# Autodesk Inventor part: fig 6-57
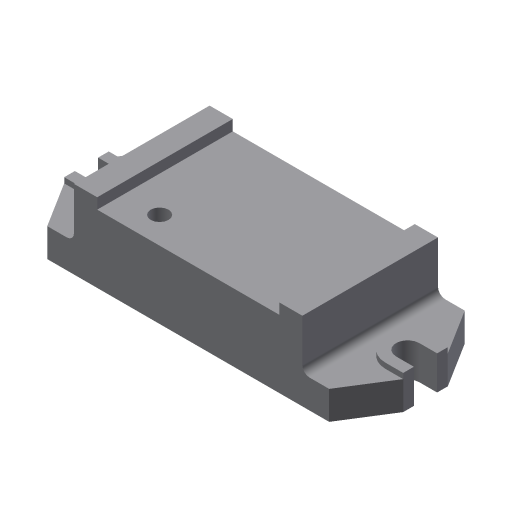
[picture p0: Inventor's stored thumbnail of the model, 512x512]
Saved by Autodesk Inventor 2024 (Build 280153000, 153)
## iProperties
Shininess: 77.0
Angle Display Precision: 2
Document Length Units: 11269
Document Angle Units: 11279
Document Time Units: 11290
Document Mass Units: 11283
Document Length Units Precision: 3
Document Angle Units Precision: 2
Created: 2001-12
Part Number: fig 6-57
Document SubType Name: Modeling
Designer: Renu Muthoo
Density: 1 g/cm^3
Material: Generic
Appearance: Default
Density: 0.0
Volumn: 0.0
Area: 0.0
PropertySet Name: Model Information
Control State: 0
Master: False
Checked Out: False
Author: Renu Muthoo
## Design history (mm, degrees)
sketch "Sketch3"
  geometry: L1 (-59.119, -24.322)-(-59.119, 19.678); L2 (-59.119, 19.678)-(-46.119, 19.678); L3 (-46.119, 19.678)-(-46.119, 13.678); L4 (-46.119, 13.678)-(55.881, 13.678); L5 (55.881, 13.678)-(55.881, 19.678); L6 (55.881, 19.678)-(68.881, 19.678); L7 (68.881, 19.678)-(68.881, -24.322); L8 (68.881, -24.322)-(-59.119, -24.322)
  constraints: 16 end point, 2 equal length
  dimensions: "d10" = 13 distance of L1.end L2.end; "d11" = 102 distance of L3.end L4.end; "d13" = 44 distance between parallel lines of L2 L8; "d14" = 6 distance of L2.end L3.end
extrude "Extrusion1" new body sketch "Sketch3" distance "d15" = 76; taper "d16" = 0 deg
sketch "Sketch4"
  geometry: L1 (0, 0)-(0, 76) reference; L2 (0, 76)-(-15, 76); L3 (-15, 76)-(-31, 50.5); L4 (-31, 50.5)-(-31, 44.5); L5 (-31, 44.5)-(-21, 44.5); L6 (-21, 31.5)-(-31, 31.5); L7 (-31, 31.5)-(-31, 25.5); L8 (-31, 25.5)-(-15, 0); L9 (-15, 0)-(0, 0); L10 (128, 76)-(0, 76) reference; L11 (0, 0)-(128, 0) reference; A1 r 6.5 centre (-21, 38) between (-21, 31.5) and (-21, 44.5)
  constraints: 16 end point, 4 equal length, 3 collinear, 3 parallel, 2 perpendicular, 2 point on circle, 2 tangent, 1 centre point
  dimensions: "d17" = 13 distance between parallel lines of L6 L5; "d18" = 25 distance of L3.end L7.end; "d19" = 10 distance of L6.start L6.end; "d20" = 15 distance of L8.end L1.start; "d21" = 16 horizontal distance of L7.end L8.end
extrude "Extrusion2" join sketch "Sketch4" distance "d22" = 16; taper "d23" = 0 deg
sketch "Sketch5"
  geometry: L1 (-159, 44.5)-(-159, 50.5) reference; L2 (-149, 44.5)-(-159, 44.5) reference; L3 (-159, 31.5)-(-149, 31.5) reference; L4 (-159, 25.5)-(-159, 31.5) reference; L5 (-159, 25.5)-(-149, 25.5); L6 (-149, 50.5)-(-159, 50.5); A1 r 6.5 centre (-149, 38) between (-149, 31.5) and (-149, 44.5) reference; A2 r 12.5 centre (-149, 38) between (-149, 25.5) and (-149, 50.5)
  constraints: 4 end point, 2 point on circle, 2 tangent, 1 centre point, 1 parallel, 1 perpendicular
extrude "Extrusion3" join sketch "Sketch5" distance "d24" = 19; taper "d25" = 0 deg
workplane "Work Plane1"
mirror "Mirror1"
fillet "Fillet1" dims "d27" = 4
sketch "Sketch6"
  geometry: L1 (0, 0)-(0, 76) reference; L2 (0, 0)-(102, 0) reference; 1 further point
  dimensions: "d28" = 20 distance from line of L1 point (20, 15); "d29" = 15 distance from line of L2 point (20, 15)
hole "Hole1" sketch "Sketch6" diameter "d30" = 10; stored, may be unused: countersink angle "d34" = 82 deg, drill point angle "d36" = 118 deg; dims "d31" = 6, "d32" = 4, "d33" = 2, "d35" = 15
sketch "Sketch7"
  geometry: C1 r 5 at (20, 15) reference; 3 further points
  constraints: 4 other
body "Solid1"
other parameters: "d26" = -64
